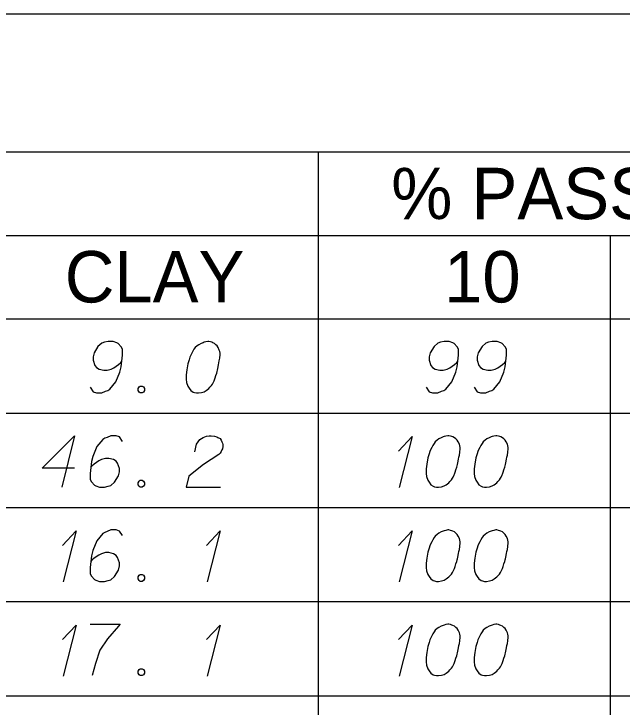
# Model space of a CAD drawing. Extents: x 2074207 to 2076812, y 516372 to 523312.
# Drawn here: x 2076621.8 to 2076678.5, y 517882.7 to 517947.4 of the extents above; entities that cross this region are included whole.
import ezdxf

# ---------------------------------------------------------------- set-up
doc = ezdxf.new("R2010")
doc.units = 0
for name, color, linetype in [('Prop DirtTable_ Soil Test Results - Outline (Major)', 7, 'Continuous'), ('Prop DirtTable_ Soil Test Results - Outline (Minor)', 7, 'Continuous'), ('Prop DirtTable_ Soil Test Results - Tx (Header - Small)', 7, 'Continuous'), ('Prop DirtTable_ Soil Test Results - Tx (Sample Data)', 7, 'Continuous')]:
    doc.layers.add(name, color=color, linetype=linetype)

msp = doc.modelspace()

# ---------------------------------------------------------------- linework, layer by layer
at = {"layer": 'Prop DirtTable_ Soil Test Results - Outline (Major)'}
for p, q in [((2076260.609, 517947.403), (2076811.903, 517947.403)), ((2076260.609, 517918.918), (2076811.903, 517918.918)), ((2076260.609, 517918.918), (2076811.903, 517918.918))]:
    msp.add_line(p, q, dxfattribs=at)
at = {"layer": 'Prop DirtTable_ Soil Test Results - Outline (Minor)'}
for p, q in [((2076260.609, 517934.518), (2076811.903, 517934.518)), ((2076650.154, 517934.518), (2076650.154, 517910.118)), ((2076526.074, 517926.718), (2076731.93, 517926.718)), ((2076677.413, 517926.718), (2076677.413, 517910.118)), ((2076260.609, 517910.118), (2076811.903, 517910.118)), ((2076260.609, 517910.118), (2076811.903, 517910.118)), ((2076650.154, 517910.118), (2076650.154, 517901.318)), ((2076677.413, 517910.118), (2076677.413, 517901.318)), ((2076260.609, 517901.318), (2076811.903, 517901.318)), ((2076260.609, 517901.318), (2076811.903, 517901.318)), ((2076650.154, 517901.318), (2076650.154, 517892.518)), ((2076677.413, 517901.318), (2076677.413, 517892.518)), ((2076260.609, 517892.518), (2076811.903, 517892.518)), ((2076260.609, 517892.518), (2076811.903, 517892.518)), ((2076650.154, 517892.518), (2076650.154, 517883.718)), ((2076677.413, 517892.518), (2076677.413, 517883.718)), ((2076260.609, 517883.718), (2076811.903, 517883.718)), ((2076260.609, 517883.718), (2076811.903, 517883.718)), ((2076650.154, 517883.718), (2076650.154, 517874.918)), ((2076677.413, 517883.718), (2076677.413, 517874.918))]:
    msp.add_line(p, q, dxfattribs=at)
at = {"layer": 'Prop DirtTable_ Soil Test Results - Tx (Sample Data)'}
for points in [[(2076628.876, 517912.536), (2076629.158, 517912.12), (2076629.475, 517912.007), (2076629.969, 517912.007), (2076630.322, 517912.158), (2076630.534, 517912.234), (2076630.71, 517912.347), (2076631.274, 517913.027), (2076631.662, 517913.934), (2076631.768, 517914.426), (2076631.909, 517915.522), (2076631.909, 517916.089), (2076631.768, 517916.315), (2076631.486, 517916.618), (2076631.38, 517916.693), (2076631.027, 517916.807), (2076630.569, 517916.807), (2076630.216, 517916.731), (2076629.969, 517916.656), (2076629.616, 517916.353), (2076629.264, 517915.749), (2076629.158, 517915.371), (2076629.158, 517915.068), (2076629.334, 517914.577), (2076629.475, 517914.388), (2076629.722, 517914.237), (2076630.146, 517914.123), (2076630.463, 517914.123), (2076630.851, 517914.237), (2076631.098, 517914.35), (2076631.521, 517914.652), (2076631.733, 517914.841), (2076631.839, 517914.955)], [(2076639.952, 517916.807), (2076639.882, 517916.807), (2076639.67, 517916.769), (2076639.529, 517916.731), (2076639.423, 517916.693), (2076639.247, 517916.618), (2076639.035, 517916.504), (2076638.859, 517916.391), (2076638.682, 517916.24), (2076638.576, 517916.089), (2076638.471, 517915.9), (2076638.365, 517915.711), (2076638.259, 517915.484), (2076638.188, 517915.333), (2076638.118, 517915.106), (2076638.012, 517914.728), (2076637.906, 517914.161), (2076637.836, 517913.708), (2076637.836, 517913.292), (2076637.871, 517912.989), (2076638.012, 517912.649), (2076638.118, 517912.46), (2076638.294, 517912.234), (2076638.506, 517912.082), (2076638.612, 517912.045), (2076638.823, 517912.007), (2076639, 517912.007), (2076639.282, 517912.045), (2076639.529, 517912.12), (2076639.705, 517912.234), (2076639.952, 517912.423), (2076640.058, 517912.536), (2076640.199, 517912.687), (2076640.305, 517912.838), (2076640.375, 517912.952), (2076640.446, 517913.141), (2076640.481, 517913.216), (2076640.552, 517913.405), (2076640.622, 517913.632), (2076640.693, 517913.859), (2076640.728, 517914.01), (2076640.763, 517914.123), (2076640.799, 517914.275), (2076640.869, 517914.615), (2076640.905, 517914.804), (2076640.94, 517914.993), (2076640.975, 517915.257), (2076641.01, 517915.597), (2076641.01, 517915.711), (2076640.975, 517915.862), (2076640.94, 517916.013), (2076640.834, 517916.24), (2076640.728, 517916.391), (2076640.622, 517916.504), (2076640.481, 517916.618), (2076640.34, 517916.693), (2076640.234, 517916.731), (2076640.129, 517916.769), (2076639.952, 517916.807)], [(2076660.236, 517912.536), (2076660.518, 517912.12), (2076660.835, 517912.007), (2076661.329, 517912.007), (2076661.682, 517912.158), (2076661.894, 517912.234), (2076662.07, 517912.347), (2076662.634, 517913.027), (2076663.022, 517913.934), (2076663.128, 517914.426), (2076663.269, 517915.522), (2076663.269, 517916.089), (2076663.128, 517916.315), (2076662.846, 517916.618), (2076662.74, 517916.693), (2076662.387, 517916.807), (2076661.929, 517916.807), (2076661.576, 517916.731), (2076661.329, 517916.656), (2076660.976, 517916.353), (2076660.624, 517915.749), (2076660.518, 517915.371), (2076660.518, 517915.068), (2076660.694, 517914.577), (2076660.835, 517914.388), (2076661.082, 517914.237), (2076661.506, 517914.123), (2076661.823, 517914.123), (2076662.211, 517914.237), (2076662.458, 517914.35), (2076662.881, 517914.652), (2076663.093, 517914.841), (2076663.199, 517914.955)], [(2076664.716, 517912.536), (2076664.998, 517912.12), (2076665.315, 517912.007), (2076665.809, 517912.007), (2076666.162, 517912.158), (2076666.374, 517912.234), (2076666.55, 517912.347), (2076667.114, 517913.027), (2076667.502, 517913.934), (2076667.608, 517914.426), (2076667.749, 517915.522), (2076667.749, 517916.089), (2076667.608, 517916.315), (2076667.326, 517916.618), (2076667.22, 517916.693), (2076666.867, 517916.807), (2076666.409, 517916.807), (2076666.056, 517916.731), (2076665.809, 517916.656), (2076665.456, 517916.353), (2076665.104, 517915.749), (2076664.998, 517915.371), (2076664.998, 517915.068), (2076665.174, 517914.577), (2076665.315, 517914.388), (2076665.562, 517914.237), (2076665.986, 517914.123), (2076666.303, 517914.123), (2076666.691, 517914.237), (2076666.938, 517914.35), (2076667.361, 517914.652), (2076667.573, 517914.841), (2076667.679, 517914.955)], [(2076633.567, 517912.649), (2076633.744, 517912.649), (2076633.849, 517912.574), (2076633.955, 517912.423), (2076633.955, 517912.234), (2076633.849, 517912.082), (2076633.744, 517912.007), (2076633.567, 517912.007), (2076633.461, 517912.082), (2076633.356, 517912.234), (2076633.356, 517912.423), (2076633.461, 517912.574), (2076633.567, 517912.649)], [(2076627.429, 517904.983), (2076624.396, 517904.983), (2076627.429, 517908.007), (2076626.23, 517903.207)], [(2076631.909, 517907.478), (2076631.627, 517907.893), (2076631.31, 517908.007), (2076630.816, 517908.007), (2076630.463, 517907.856), (2076630.251, 517907.78), (2076630.075, 517907.667), (2076629.511, 517906.986), (2076629.123, 517906.079), (2076629.017, 517905.588), (2076628.876, 517904.492), (2076628.876, 517903.925), (2076629.017, 517903.698), (2076629.299, 517903.396), (2076629.405, 517903.32), (2076629.758, 517903.207), (2076630.216, 517903.207), (2076630.569, 517903.282), (2076630.816, 517903.358), (2076631.169, 517903.66), (2076631.521, 517904.265), (2076631.627, 517904.643), (2076631.627, 517904.945), (2076631.451, 517905.437), (2076631.31, 517905.626), (2076631.063, 517905.777), (2076630.639, 517905.89), (2076630.322, 517905.89), (2076629.934, 517905.777), (2076629.687, 517905.663), (2076629.264, 517905.361), (2076629.052, 517905.172), (2076628.946, 517905.059)], [(2076638.647, 517906.495), (2076638.823, 517907.213), (2076639.106, 517907.667), (2076639.423, 517907.856), (2076639.74, 517907.969), (2076639.987, 517908.007), (2076640.164, 517908.007), (2076640.481, 517907.969), (2076640.693, 517907.893), (2076640.799, 517907.856), (2076641.01, 517907.742), (2076641.116, 517907.591), (2076641.187, 517907.44), (2076641.222, 517907.326), (2076641.257, 517907.175), (2076641.257, 517906.986), (2076641.222, 517906.797), (2076641.187, 517906.684), (2076641.116, 517906.533), (2076641.01, 517906.382), (2076640.905, 517906.268), (2076639.458, 517905.323), (2076638.083, 517904.227), (2076637.836, 517903.207), (2076641.046, 517903.207)], [(2076657.66, 517906.571), (2076658.93, 517907.931), (2076657.731, 517903.169)], [(2076662.352, 517908.007), (2076662.282, 517908.007), (2076662.07, 517907.969), (2076661.929, 517907.931), (2076661.823, 517907.893), (2076661.647, 517907.818), (2076661.435, 517907.704), (2076661.259, 517907.591), (2076661.082, 517907.44), (2076660.976, 517907.289), (2076660.871, 517907.1), (2076660.765, 517906.911), (2076660.659, 517906.684), (2076660.588, 517906.533), (2076660.518, 517906.306), (2076660.412, 517905.928), (2076660.306, 517905.361), (2076660.236, 517904.908), (2076660.236, 517904.492), (2076660.271, 517904.189), (2076660.412, 517903.849), (2076660.518, 517903.66), (2076660.694, 517903.434), (2076660.906, 517903.282), (2076661.012, 517903.245), (2076661.223, 517903.207), (2076661.4, 517903.207), (2076661.682, 517903.245), (2076661.929, 517903.32), (2076662.105, 517903.434), (2076662.352, 517903.623), (2076662.458, 517903.736), (2076662.599, 517903.887), (2076662.705, 517904.038), (2076662.775, 517904.152), (2076662.846, 517904.341), (2076662.881, 517904.416), (2076662.952, 517904.605), (2076663.022, 517904.832), (2076663.093, 517905.059), (2076663.128, 517905.21), (2076663.163, 517905.323), (2076663.199, 517905.475), (2076663.269, 517905.815), (2076663.305, 517906.004), (2076663.34, 517906.193), (2076663.375, 517906.457), (2076663.41, 517906.797), (2076663.41, 517906.911), (2076663.375, 517907.062), (2076663.34, 517907.213), (2076663.234, 517907.44), (2076663.128, 517907.591), (2076663.022, 517907.704), (2076662.881, 517907.818), (2076662.74, 517907.893), (2076662.634, 517907.931), (2076662.529, 517907.969), (2076662.352, 517908.007)], [(2076666.832, 517908.007), (2076666.762, 517908.007), (2076666.55, 517907.969), (2076666.409, 517907.931), (2076666.303, 517907.893), (2076666.127, 517907.818), (2076665.915, 517907.704), (2076665.739, 517907.591), (2076665.562, 517907.44), (2076665.456, 517907.289), (2076665.351, 517907.1), (2076665.245, 517906.911), (2076665.139, 517906.684), (2076665.068, 517906.533), (2076664.998, 517906.306), (2076664.892, 517905.928), (2076664.786, 517905.361), (2076664.716, 517904.908), (2076664.716, 517904.492), (2076664.751, 517904.189), (2076664.892, 517903.849), (2076664.998, 517903.66), (2076665.174, 517903.434), (2076665.386, 517903.282), (2076665.492, 517903.245), (2076665.703, 517903.207), (2076665.88, 517903.207), (2076666.162, 517903.245), (2076666.409, 517903.32), (2076666.585, 517903.434), (2076666.832, 517903.623), (2076666.938, 517903.736), (2076667.079, 517903.887), (2076667.185, 517904.038), (2076667.255, 517904.152), (2076667.326, 517904.341), (2076667.361, 517904.416), (2076667.432, 517904.605), (2076667.502, 517904.832), (2076667.573, 517905.059), (2076667.608, 517905.21), (2076667.643, 517905.323), (2076667.679, 517905.475), (2076667.749, 517905.815), (2076667.785, 517906.004), (2076667.82, 517906.193), (2076667.855, 517906.457), (2076667.89, 517906.797), (2076667.89, 517906.911), (2076667.855, 517907.062), (2076667.82, 517907.213), (2076667.714, 517907.44), (2076667.608, 517907.591), (2076667.502, 517907.704), (2076667.361, 517907.818), (2076667.22, 517907.893), (2076667.114, 517907.931), (2076667.009, 517907.969), (2076666.832, 517908.007)], [(2076633.567, 517903.849), (2076633.744, 517903.849), (2076633.849, 517903.774), (2076633.955, 517903.623), (2076633.955, 517903.434), (2076633.849, 517903.282), (2076633.744, 517903.207), (2076633.567, 517903.207), (2076633.461, 517903.282), (2076633.356, 517903.434), (2076633.356, 517903.623), (2076633.461, 517903.774), (2076633.567, 517903.849)], [(2076626.3, 517897.771), (2076627.57, 517899.131), (2076626.371, 517894.369)], [(2076631.909, 517898.678), (2076631.627, 517899.093), (2076631.31, 517899.207), (2076630.816, 517899.207), (2076630.463, 517899.056), (2076630.251, 517898.98), (2076630.075, 517898.867), (2076629.511, 517898.186), (2076629.123, 517897.279), (2076629.017, 517896.788), (2076628.876, 517895.692), (2076628.876, 517895.125), (2076629.017, 517894.898), (2076629.299, 517894.596), (2076629.405, 517894.52), (2076629.758, 517894.407), (2076630.216, 517894.407), (2076630.569, 517894.482), (2076630.816, 517894.558), (2076631.169, 517894.86), (2076631.521, 517895.465), (2076631.627, 517895.843), (2076631.627, 517896.145), (2076631.451, 517896.637), (2076631.31, 517896.826), (2076631.063, 517896.977), (2076630.639, 517897.09), (2076630.322, 517897.09), (2076629.934, 517896.977), (2076629.687, 517896.863), (2076629.264, 517896.561), (2076629.052, 517896.372), (2076628.946, 517896.259)], [(2076639.74, 517897.771), (2076641.01, 517899.131), (2076639.811, 517894.369)], [(2076657.66, 517897.771), (2076658.93, 517899.131), (2076657.731, 517894.369)], [(2076662.352, 517899.207), (2076662.282, 517899.207), (2076662.07, 517899.169), (2076661.929, 517899.131), (2076661.823, 517899.093), (2076661.647, 517899.018), (2076661.435, 517898.904), (2076661.259, 517898.791), (2076661.082, 517898.64), (2076660.976, 517898.489), (2076660.871, 517898.3), (2076660.765, 517898.111), (2076660.659, 517897.884), (2076660.588, 517897.733), (2076660.518, 517897.506), (2076660.412, 517897.128), (2076660.306, 517896.561), (2076660.236, 517896.108), (2076660.236, 517895.692), (2076660.271, 517895.389), (2076660.412, 517895.049), (2076660.518, 517894.86), (2076660.694, 517894.634), (2076660.906, 517894.482), (2076661.012, 517894.445), (2076661.223, 517894.407), (2076661.4, 517894.407), (2076661.682, 517894.445), (2076661.929, 517894.52), (2076662.105, 517894.634), (2076662.352, 517894.823), (2076662.458, 517894.936), (2076662.599, 517895.087), (2076662.705, 517895.238), (2076662.775, 517895.352), (2076662.846, 517895.541), (2076662.881, 517895.616), (2076662.952, 517895.805), (2076663.022, 517896.032), (2076663.093, 517896.259), (2076663.128, 517896.41), (2076663.163, 517896.523), (2076663.199, 517896.675), (2076663.269, 517897.015), (2076663.305, 517897.204), (2076663.34, 517897.393), (2076663.375, 517897.657), (2076663.41, 517897.997), (2076663.41, 517898.111), (2076663.375, 517898.262), (2076663.34, 517898.413), (2076663.234, 517898.64), (2076663.128, 517898.791), (2076663.022, 517898.904), (2076662.881, 517899.018), (2076662.74, 517899.093), (2076662.634, 517899.131), (2076662.529, 517899.169), (2076662.352, 517899.207)], [(2076666.832, 517899.207), (2076666.762, 517899.207), (2076666.55, 517899.169), (2076666.409, 517899.131), (2076666.303, 517899.093), (2076666.127, 517899.018), (2076665.915, 517898.904), (2076665.739, 517898.791), (2076665.562, 517898.64), (2076665.456, 517898.489), (2076665.351, 517898.3), (2076665.245, 517898.111), (2076665.139, 517897.884), (2076665.068, 517897.733), (2076664.998, 517897.506), (2076664.892, 517897.128), (2076664.786, 517896.561), (2076664.716, 517896.108), (2076664.716, 517895.692), (2076664.751, 517895.389), (2076664.892, 517895.049), (2076664.998, 517894.86), (2076665.174, 517894.634), (2076665.386, 517894.482), (2076665.492, 517894.445), (2076665.703, 517894.407), (2076665.88, 517894.407), (2076666.162, 517894.445), (2076666.409, 517894.52), (2076666.585, 517894.634), (2076666.832, 517894.823), (2076666.938, 517894.936), (2076667.079, 517895.087), (2076667.185, 517895.238), (2076667.255, 517895.352), (2076667.326, 517895.541), (2076667.361, 517895.616), (2076667.432, 517895.805), (2076667.502, 517896.032), (2076667.573, 517896.259), (2076667.608, 517896.41), (2076667.643, 517896.523), (2076667.679, 517896.675), (2076667.749, 517897.015), (2076667.785, 517897.204), (2076667.82, 517897.393), (2076667.855, 517897.657), (2076667.89, 517897.997), (2076667.89, 517898.111), (2076667.855, 517898.262), (2076667.82, 517898.413), (2076667.714, 517898.64), (2076667.608, 517898.791), (2076667.502, 517898.904), (2076667.361, 517899.018), (2076667.22, 517899.093), (2076667.114, 517899.131), (2076667.009, 517899.169), (2076666.832, 517899.207)], [(2076633.567, 517895.049), (2076633.744, 517895.049), (2076633.849, 517894.974), (2076633.955, 517894.823), (2076633.955, 517894.634), (2076633.849, 517894.482), (2076633.744, 517894.407), (2076633.567, 517894.407), (2076633.461, 517894.482), (2076633.356, 517894.634), (2076633.356, 517894.823), (2076633.461, 517894.974), (2076633.567, 517895.049)], [(2076626.3, 517888.971), (2076627.57, 517890.331), (2076626.371, 517885.569)], [(2076628.876, 517890.407), (2076631.698, 517890.407), (2076631.521, 517890.218), (2076630.498, 517889.046), (2076629.793, 517887.988), (2076629.369, 517886.741), (2076629.087, 517885.607)], [(2076639.74, 517888.971), (2076641.01, 517890.331), (2076639.811, 517885.569)], [(2076657.66, 517888.971), (2076658.93, 517890.331), (2076657.731, 517885.569)], [(2076662.352, 517890.407), (2076662.282, 517890.407), (2076662.07, 517890.369), (2076661.929, 517890.331), (2076661.823, 517890.293), (2076661.647, 517890.218), (2076661.435, 517890.104), (2076661.259, 517889.991), (2076661.082, 517889.84), (2076660.976, 517889.689), (2076660.871, 517889.5), (2076660.765, 517889.311), (2076660.659, 517889.084), (2076660.588, 517888.933), (2076660.518, 517888.706), (2076660.412, 517888.328), (2076660.306, 517887.761), (2076660.236, 517887.308), (2076660.236, 517886.892), (2076660.271, 517886.589), (2076660.412, 517886.249), (2076660.518, 517886.06), (2076660.694, 517885.834), (2076660.906, 517885.682), (2076661.012, 517885.645), (2076661.223, 517885.607), (2076661.4, 517885.607), (2076661.682, 517885.645), (2076661.929, 517885.72), (2076662.105, 517885.834), (2076662.352, 517886.023), (2076662.458, 517886.136), (2076662.599, 517886.287), (2076662.705, 517886.438), (2076662.775, 517886.552), (2076662.846, 517886.741), (2076662.881, 517886.816), (2076662.952, 517887.005), (2076663.022, 517887.232), (2076663.093, 517887.459), (2076663.128, 517887.61), (2076663.163, 517887.723), (2076663.199, 517887.875), (2076663.269, 517888.215), (2076663.305, 517888.404), (2076663.34, 517888.593), (2076663.375, 517888.857), (2076663.41, 517889.197), (2076663.41, 517889.311), (2076663.375, 517889.462), (2076663.34, 517889.613), (2076663.234, 517889.84), (2076663.128, 517889.991), (2076663.022, 517890.104), (2076662.881, 517890.218), (2076662.74, 517890.293), (2076662.634, 517890.331), (2076662.529, 517890.369), (2076662.352, 517890.407)], [(2076666.832, 517890.407), (2076666.762, 517890.407), (2076666.55, 517890.369), (2076666.409, 517890.331), (2076666.303, 517890.293), (2076666.127, 517890.218), (2076665.915, 517890.104), (2076665.739, 517889.991), (2076665.562, 517889.84), (2076665.456, 517889.689), (2076665.351, 517889.5), (2076665.245, 517889.311), (2076665.139, 517889.084), (2076665.068, 517888.933), (2076664.998, 517888.706), (2076664.892, 517888.328), (2076664.786, 517887.761), (2076664.716, 517887.308), (2076664.716, 517886.892), (2076664.751, 517886.589), (2076664.892, 517886.249), (2076664.998, 517886.06), (2076665.174, 517885.834), (2076665.386, 517885.682), (2076665.492, 517885.645), (2076665.703, 517885.607), (2076665.88, 517885.607), (2076666.162, 517885.645), (2076666.409, 517885.72), (2076666.585, 517885.834), (2076666.832, 517886.023), (2076666.938, 517886.136), (2076667.079, 517886.287), (2076667.185, 517886.438), (2076667.255, 517886.552), (2076667.326, 517886.741), (2076667.361, 517886.816), (2076667.432, 517887.005), (2076667.502, 517887.232), (2076667.573, 517887.459), (2076667.608, 517887.61), (2076667.643, 517887.723), (2076667.679, 517887.875), (2076667.749, 517888.215), (2076667.785, 517888.404), (2076667.82, 517888.593), (2076667.855, 517888.857), (2076667.89, 517889.197), (2076667.89, 517889.311), (2076667.855, 517889.462), (2076667.82, 517889.613), (2076667.714, 517889.84), (2076667.608, 517889.991), (2076667.502, 517890.104), (2076667.361, 517890.218), (2076667.22, 517890.293), (2076667.114, 517890.331), (2076667.009, 517890.369), (2076666.832, 517890.407)], [(2076633.567, 517886.249), (2076633.744, 517886.249), (2076633.849, 517886.174), (2076633.955, 517886.023), (2076633.955, 517885.834), (2076633.849, 517885.682), (2076633.744, 517885.607), (2076633.567, 517885.607), (2076633.461, 517885.682), (2076633.356, 517885.834), (2076633.356, 517886.023), (2076633.461, 517886.174), (2076633.567, 517886.249)]]:
    msp.add_lwpolyline(points, dxfattribs=at)

# ---------------------------------------------------------------- texts
at = {"layer": 'Prop DirtTable_ Soil Test Results - Tx (Header - Small)'}
for s, height, p in [('% PASSING (SIEVES)', 4.79998, (2076656.984, 517928.228)), ('CLAY', 4.8, (2076626.513, 517920.453)), ('10', 4.8, (2076661.92, 517920.453))]:
    msp.add_text(s, height=height, dxfattribs=at).set_placement(p)

doc.saveas('drawing.dxf')
